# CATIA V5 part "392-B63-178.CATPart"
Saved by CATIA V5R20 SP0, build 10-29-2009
Part number: 392-B63-178
Definition: NONE
Nomenclature: 392-B63-178
Source: Unknown
Description: 392-B63-178
Bounding box of the stored display mesh (mm): x 0 to 178, y -31.407 to 31.407, z -31.1 to 31.1
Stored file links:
  C:\Users\Utente\Desktop\IO LAVORO\3D X SITO CF\X SITO\3D files 392B\392-B63-178.CATPart
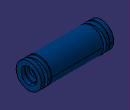
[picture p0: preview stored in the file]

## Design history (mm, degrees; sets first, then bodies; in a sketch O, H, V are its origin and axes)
Body1 "392-B63-178" (main body)
  Solid1: solid without history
